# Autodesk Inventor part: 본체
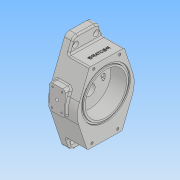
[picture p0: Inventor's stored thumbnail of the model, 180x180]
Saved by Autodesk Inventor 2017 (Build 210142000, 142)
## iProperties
Part Number: 본체
Material: 일반
Document SubType Name: Modeling
Designer: Administrator
Density: 1 g/cm^3
Appearance: 기본값
Author: Administrator
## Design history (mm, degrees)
sketch "스케치1"
  geometry: L1 (-51.832, 18.401)-(-24.317, 94); L2 (-24.317, 94)-(24.317, 94); L3 (24.317, 94)-(51.683, 18.811); L4 (-55, 0)-(55, 0); L5 (-33.78, 68)-(33.78, 68); L6 (-51.832, -18.401)-(-24.317, -94); L7 (-24.317, -94)-(24.317, -94); L8 (24.317, -94)-(51.683, -18.811); L9 (-33.78, -68)-(33.78, -68); A1 r 55 centre (0, 0) between (-51.683, 18.811) and (-55, 0); A2 r 55 centre (0, 0) between (-55, 0) and (-51.683, -18.811); A3 r 55 centre (0, 0) between (51.683, -18.811) and (51.683, 18.811); 3 further points
  constraints: 18 end point, 9 point on circle, 7 symmetric about line, 6 point on line, 5 tangent, 3 centre point, 3 horizontal, 1 coincident, 1 midpoint, 1 vertical alignment
  dimensions: "d2" = 40 deg angle of L3 L1; "d3" = 94 distance from line of point (0, 0) L2; "d4" = 110 distance of L4.start L4.end; "d5" = 68 distance between parallel lines of L4 L5
extrude "돌출1" new body sketch "스케치1" distance "d6" = 55; taper "d7" = 0 deg
extrude "돌출2" join sketch "스케치1" distance "d8" = 15; taper "d9" = 0 deg
sketch "스케치2"
  geometry: L1 (-94, 0)-(-94, 15) reference; L2 (-94, 15)-(-68, 15) reference; L3 (-68, 15)-(-68, 55) reference; L4 (-68, 55)-(68, 55) reference; L5 (68, 55)-(68, 15) reference; L6 (68, 15)-(94, 15) reference; L7 (94, 15)-(94, 0) reference; L8 (94, 0)-(-94, 0) reference; L9 (-94, 0)-(-94, 15) reference; L10 (-94, 15)-(-68, 15) reference; L11 (-68, 15)-(-68, 55) reference; L12 (-68, 55)-(68, 55) reference; L13 (68, 55)-(68, 15) reference; L14 (68, 15)-(94, 15) reference; L15 (94, 15)-(94, 0) reference; L16 (94, 0)-(-94, 0) reference; L17 (18.811, 55)-(-18.811, 55) reference; L18 (9, 0)-(9, 55); L19 (18.811, 55)-(68, 55) reference; L20 (49, 55)-(49, 25); L21 (49, 25)-(9, 25); L22 (49, 55)-(9, 55); 1 further point
  constraints: 8 end point, 4 point on line, 3 perpendicular, 1 collinear
  dimensions: "d10" = 9 distance from line of point (0, 0) L18; "d11" = 30 distance of L20.start L20.end; "d12" = 80 diameter of L20 L18
revolve "회전1" sketch "스케치2" stored, may be unused: angle "d13" = 90 deg
sketch "스케치8"
  geometry: L1 (-51.683, 18.811)-(-24.317, 94) reference; L2 (-24.317, 94)-(24.317, 94) reference; L3 (24.317, 94)-(51.683, 18.811) reference; L4 (51.683, -18.811)-(24.317, -94) reference; L5 (24.317, -94)-(-24.317, -94) reference; L6 (-24.317, -94)-(-51.683, -18.811) reference; C1 r 17.5 at (0, 0); A1 r 55 centre (0, 0) between (-51.683, 18.811) and (-51.683, -18.811) reference; A2 r 55 centre (0, 0) between (51.683, -18.811) and (51.683, 18.811) reference
  constraints: 1 centre point, 1 coincident
  dimensions: "d34" = 35 diameter of C1
extrude "돌출4" join sketch "스케치8" distance "d35" = 5; taper "d36" = 0 deg
sketch "스케치9"
  geometry: L1 (-94, 0)-(-94, 15) reference; L2 (-94, 15)-(-68, 15) reference; L3 (-68, 15)-(-68, 55) reference; L4 (-68, 55)-(-31, 55) reference; L5 (-31, 55)-(-31, 25) reference; L6 (-31, 25)-(49, 25) reference; L7 (49, 25)-(49, 55) reference; L8 (49, 55)-(68, 55) reference; L9 (68, 55)-(68, 15) reference; L10 (68, 15)-(94, 15) reference; L11 (94, 15)-(94, 0) reference; L12 (94, 0)-(17.5, 0) reference; L13 (17.5, 0)-(17.5, -5) reference; L14 (17.5, -5)-(-17.5, -5) reference; L15 (-17.5, -5)-(-17.5, 0) reference; L16 (-17.5, 0)-(-94, 0) reference; L17 (-17.5, -5)-(17.5, -5) reference; L18 (12.5, -5)-(12.5, 3.2); L19 (12.3, 3.4)-(8, 3.4); L20 (8, 3.4)-(8, 15); L21 (8, 15)-(10, 15); L22 (10, 15)-(10, 25); L23 (0, -5)-(0, 25); L24 (12.5, -5)-(0, -5); L25 (10, 25)-(0, 25); A1 r 0.2 centre (12.3, 3.2) between (12.5, 3.2) and (12.3, 3.4); 1 further point
  constraints: 16 end point, 4 perpendicular, 3 point on line, 2 collinear, 2 point on circle, 2 tangent, 2 vertical, 1 centre point, 1 midpoint
  dimensions: "d37" = 8.4 distance between parallel lines of L24 L19; "d38" = 10 distance between parallel lines of L25 L21; "d40" = 25 diameter of L18 L23; "d41" = 20 diameter of L22 L23; "d42" = 16 diameter of L20 L23; "d43" = 0.2 radius of A1 (derived)
revolve "회전3" sketch "스케치9" stored, may be unused: angle "d44" = 90 deg
node "작업 평면2"
sketch "스케치6"
  geometry: L1 (32, 35)-(-14, 35); L2 (-14, 35)-(-14, 5); L3 (-14, 5)-(32, 5); L4 (32, 5)-(32, 35); L5 (32, 35)-(-14, 5); L6 (-14, 35)-(32, 5); L7 (18.811, 0)-(-18.811, 0) reference; 2 further points
  constraints: 12 end point, 2 midpoint, 2 parallel, 1 horizontal, 1 perpendicular
  dimensions: "d26" = 30 distance of L3.end L1.start; "d27" = 46 distance of L2.end L3.end; "d29" = 20 distance from line of L7 point (9, 20); "d30" = 9 horizontal distance of point (0, 0) point (9, 20)
extrude "돌출3" join sketch "스케치6" stored distance "d31" = 4; taper "d32" = 0 deg
sketch "스케치10"
  geometry: L1 (33.78, -68)-(-33.78, -68) reference; L2 (-33.78, -68)-(-51.683, -18.811) reference; L3 (-51.683, 18.811)-(-33.78, 68) reference; L4 (-33.78, 68)-(33.78, 68) reference; L5 (33.78, 68)-(51.683, 18.811) reference; L6 (51.683, -18.811)-(33.78, -68) reference; L7 (33.78, -68)-(-33.78, -68) reference; L8 (-33.78, -68)-(-51.683, -18.811) reference; L9 (-51.683, 18.811)-(-33.78, 68) reference; L10 (-33.78, 68)-(33.78, 68) reference; L11 (33.78, 68)-(51.683, 18.811) reference; L12 (51.683, -18.811)-(33.78, -68) reference; C1 r 40 at (0, 9) reference; C2 r 40 at (0, 9) reference; C3 r 47.5 at (0, 9); C4 r 43.4 at (0, 9); A1 r 55 centre (0, 0) between (-51.683, 18.811) and (-51.683, -18.811) reference; A2 r 55 centre (0, 0) between (51.683, -18.811) and (51.683, 18.811) reference; A3 r 55 centre (0, 0) between (-51.683, 18.811) and (-51.683, -18.811) reference; A4 r 55 centre (0, 0) between (51.683, -18.811) and (51.683, 18.811) reference
  constraints: 2 centre point, 1 coincident
  dimensions: "d45" = 95 diameter of C3; "d46" = 4.1 radial gap between concentric circles of C3 C4
extrude "돌출5" cut sketch "스케치10" distance "d47" = 2.4; taper "d48" = 0 deg
sketch "스케치11"
  geometry: L1 (33.78, -77)-(-33.78, -77) reference; L2 (-33.78, -77)-(-51.683, -27.811) reference; L3 (-53.188, -23)-(-59, -23) reference; L4 (-59, -23)-(-59, 23) reference; L5 (-59, 23)-(-46.883, 23) reference; L6 (-46.883, 23)-(-33.78, 59) reference; L7 (-33.78, 59)-(33.78, 59) reference; L8 (33.78, 59)-(46.883, 23) reference; L9 (46.883, 23)-(59, 23) reference; L10 (59, 23)-(59, -23) reference; L11 (59, -23)-(53.188, -23) reference; L12 (51.683, -27.811)-(33.78, -77) reference; L13 (-26.702, -6)-(-25.515, -6); L14 (25.515, -6)-(26.702, -6); L15 (-26.702, 6)-(-22.517, 6); L16 (22.517, 6)-(26.702, 6); C1 r 40 at (0, 0) reference; C2 r 40 at (0, 0) reference; C3 r 10 at (0, -9) reference; C4 r 10 at (0, -9) reference; A1 r 55 centre (0, -9) between (-53.188, -23) and (-51.683, -27.811) reference; A2 r 55 centre (0, -9) between (51.683, -27.811) and (53.188, -23) reference; A3 r 24 centre (0, -9) between (-20.785, 3) and (-23.552, -4.385); A4 r 24 centre (0, -9) between (23.552, -4.385) and (20.785, 3); A5 r 29 centre (0, 0) between (-28.68, 4.296) and (-28.68, -4.296); A6 r 29 centre (0, 0) between (28.68, -4.296) and (28.68, 4.296); A7 r 2 centre (-22.517, 4) between (-20.785, 3) and (-22.517, 6); A8 r 2 centre (-26.702, 4) between (-26.702, 6) and (-28.68, 4.296); A9 r 2 centre (-26.702, -4) between (-28.68, -4.296) and (-26.702, -6); A10 r 2 centre (-25.515, -4) between (-25.515, -6) and (-23.552, -4.385); A11 r 2 centre (22.517, 4) between (22.517, 6) and (20.785, 3); A12 r 2 centre (26.702, 4) between (28.68, 4.296) and (26.702, 6); A13 r 2 centre (25.515, -4) between (23.552, -4.385) and (25.515, -6); A14 r 2 centre (26.702, -4) between (26.702, -6) and (28.68, -4.296); 8 further points
  constraints: 32 point on circle, 16 tangent, 12 centre point, 8 end point, 8 point on line, 7 equal radius, 4 horizontal, 2 coincident
  dimensions: "d53" = 6 distance from line of C1.centre L15; "d54" = 6 distance from line of C1.centre L16; "d55" = 6 distance from line of C1.centre L14; "d56" = 6 distance from line of L13 C1.centre; "d57" = 29 radius of A5; "d58" = 24 radius of A3; "d59" = 24 radius of A4; "d60" = 29 radius of A6; "d61" = 2 radius of A7
extrude "돌출6" cut sketch "스케치11" distance "d62" = 12; taper "d63" = 0 deg
sketch "스케치12"
  geometry: L1 (0, 0)-(-30, 0) reference; L2 (-30, 0)-(-30, 46) reference; L3 (-30, 46)-(0, 46) reference; L4 (0, 46)-(0, 0) reference; L5 (0, 46)-(0, 0) reference; L6 (0, 23)-(-30, 23); L7 (-30, 32.811)-(-30, 0) reference; L8 (0, 46)-(-30, 46) reference; L9 (-15, 46)-(-15, 0); C1 r 3 at (-15, 23); 1 further point
  constraints: 4 end point, 4 midpoint, 1 centre point, 1 perpendicular, 1 point on line
  dimensions: "d64" = 6 diameter of C1
extrude "돌출7" cut sketch "스케치12" stored distance "d65" = 12; taper "d66" = 0 deg; dims "d2" = 40 deg, "d3" = 94, "d4" = 110, "d5" = 68
sketch "스케치13"
  geometry: L1 (0, 0)-(-30, 0) reference; L2 (-30, 0)-(-30, 46) reference; L3 (-30, 46)-(0, 46) reference; L4 (0, 46)-(0, 0) reference; L5 (-24, 6)-(-6, 6); L6 (-6, 6)-(-6, 40); L7 (-6, 40)-(-24, 40); L8 (-24, 40)-(-24, 6); L9 (-24, 6)-(-6, 40); L10 (-6, 6)-(-24, 40); C1 r 3 at (-15, 23) reference; C2 r 3 at (-15, 23) reference; 5 further points
  constraints: 12 end point, 4 coincident, 2 midpoint, 2 parallel, 1 horizontal, 1 perpendicular
  dimensions: "d67" = 18 distance of L6.end L7.end; "d68" = 34 distance of L5.end L6.end
hole "구멍1" sketch "스케치13" at (-24, 40), (-6, 40), (-6, 6), (-24, 6) diameter "d69" = 3.242; stored, may be unused: countersink angle "d73" = 90 deg, drill point angle "d75" = 118 deg; dims "d70" = 8, "d71" = 4, "d72" = 2, "d74" = 10
sketch "스케치14"
  geometry: L1 (-22.517, 15)-(-26.702, 15) reference; L2 (-26.702, 3)-(-25.515, 3) reference; L3 (25.515, 3)-(26.702, 3) reference; L4 (26.702, 15)-(22.517, 15) reference; L5 (33.78, -68)-(-33.78, -68) reference; L6 (-24.317, -94)-(-33.78, -68) reference; L7 (24.317, -94)-(-24.317, -94) reference; L8 (33.78, -68)-(24.317, -94) reference; L9 (51.683, -18.811)-(33.78, -68) reference; L10 (59, -14)-(53.188, -14) reference; L11 (59, 32)-(59, -14) reference; L12 (46.883, 32)-(59, 32) reference; L13 (33.78, 68)-(46.883, 32) reference; L14 (-33.78, 68)-(33.78, 68) reference; L15 (-46.883, 32)-(-33.78, 68) reference; L16 (-59, 32)-(-46.883, 32) reference; L17 (-59, -14)-(-59, 32) reference; L18 (-53.188, -14)-(-59, -14) reference; L19 (-33.78, -68)-(-51.683, -18.811) reference; L20 (24.317, 94)-(33.78, 68) reference; L21 (-24.317, 94)-(24.317, 94) reference; L22 (-33.78, 68)-(-24.317, 94) reference; L23 (-20, -79)-(20, -79); L24 (20, -79)-(20, 79); L25 (20, 79)-(-20, 79); L26 (-20, 79)-(-20, -79); L27 (-20, -79)-(20, 79); L28 (20, -79)-(-20, 79); C1 r 8 at (0, 0) reference; C2 r 10 at (0, 0) reference; C3 r 12.5 at (0, 0) reference; A1 r 2 centre (-26.702, 13) between (-26.702, 15) and (-28.68, 13.296) reference; A2 r 29 centre (0, 9) between (-28.68, 13.296) and (-28.68, 4.704) reference; A3 r 2 centre (-26.702, 5) between (-28.68, 4.704) and (-26.702, 3) reference; A4 r 2 centre (-25.515, 5) between (-25.515, 3) and (-23.552, 4.615) reference; A5 r 24 centre (0, 0) between (-20.785, 12) and (-23.552, 4.615) reference; A6 r 2 centre (-22.517, 13) between (-20.785, 12) and (-22.517, 15) reference; A7 r 24 centre (0, 0) between (23.552, 4.615) and (20.785, 12) reference; A8 r 2 centre (25.515, 5) between (23.552, 4.615) and (25.515, 3) reference; A9 r 2 centre (26.702, 5) between (26.702, 3) and (28.68, 4.704) reference; A10 r 29 centre (0, 9) between (28.68, 4.704) and (28.68, 13.296) reference; A11 r 2 centre (26.702, 13) between (28.68, 13.296) and (26.702, 15) reference; A12 r 2 centre (22.517, 13) between (22.517, 15) and (20.785, 12) reference; A13 r 55 centre (0, 0) between (51.683, -18.811) and (53.188, -14) reference; A14 r 55 centre (0, 0) between (-53.188, -14) and (-51.683, -18.811) reference; 5 further points
  constraints: 12 end point, 4 coincident, 2 midpoint, 2 parallel, 1 horizontal, 1 perpendicular
  dimensions: "d76" = 40 distance of L24.end L25.end; "d77" = 158 distance of L23.end L24.end
hole "구멍2" sketch "스케치14" at (-20, 79), (20, 79), (-20, -79), (20, -79) diameter "d78" = 6.6; stored, may be unused: countersink angle "d82" = 90 deg, drill point angle "d84" = 118 deg; dims "d79" = 8, "d80" = 11, "d81" = 6.6, "d83" = 10
sketch "스케치15"
  geometry: L1 (33.78, -68)-(-33.78, -68) reference; L2 (-33.78, -68)-(-51.683, -18.811) reference; L3 (-51.683, 18.811)-(-33.78, 68) reference; L4 (-33.78, 68)-(33.78, 68) reference; L5 (33.78, 68)-(51.683, 18.811) reference; L6 (51.683, -18.811)-(33.78, -68) reference; L7 (-25, -61)-(25, -61); L8 (25, -61)-(25, 61); L9 (25, 61)-(-25, 61); L10 (-25, 61)-(-25, -61); L11 (-25, -61)-(25, 61); L12 (25, -61)-(-25, 61); C1 r 43.4 at (0, 9) reference; C2 r 47.5 at (0, 9) reference; C3 r 40 at (0, 9) reference; A1 r 55 centre (0, 0) between (-51.683, 18.811) and (-51.683, -18.811) reference; A2 r 55 centre (0, 0) between (51.683, -18.811) and (51.683, 18.811) reference; 4 further points
  constraints: 12 end point, 4 coincident, 2 midpoint, 2 parallel, 1 horizontal, 1 perpendicular
  dimensions: "d85" = 50 distance of L8.end L9.end; "d86" = 122 distance of L7.end L8.end
hole "구멍3" sketch "스케치15" at (-25, 61), (25, 61), (-25, -61), (25, -61) diameter "d87" = 4.917; stored, may be unused: countersink angle "d91" = 90 deg, drill point angle "d93" = 118 deg; dims "d88" = 12, "d89" = 11, "d90" = 6.6, "d92" = 14
sketch "스케치16"
  geometry: L1 (-22.517, 6)-(-26.702, 6) reference; L2 (-26.702, -6)-(-25.515, -6) reference; L3 (25.515, -6)-(26.702, -6) reference; L4 (26.702, 6)-(22.517, 6) reference; L5 (33.78, -77)-(-33.78, -77) reference; L6 (-33.78, -77)-(-51.683, -27.811) reference; L7 (-53.188, -23)-(-59, -23) reference; L8 (-59, -23)-(-59, 23) reference; L9 (-59, 23)-(-46.883, 23) reference; L10 (-46.883, 23)-(-33.78, 59) reference; L11 (-33.78, 59)-(33.78, 59) reference; L12 (33.78, 59)-(46.883, 23) reference; L13 (46.883, 23)-(59, 23) reference; L14 (59, 23)-(59, -23) reference; L15 (59, -23)-(53.188, -23) reference; L16 (51.683, -27.811)-(33.78, -77) reference; C1 r 40 at (0, 0) reference; C2 r 10 at (0, -9) reference; A1 r 24 centre (0, -9) between (-20.785, 3) and (-23.552, -4.385) reference; A2 r 24 centre (0, -9) between (23.552, -4.385) and (20.785, 3) reference; A3 r 2 centre (-26.702, 4) between (-26.702, 6) and (-28.68, 4.296) reference; A4 r 29 centre (0, 0) between (-28.68, 4.296) and (-28.68, -4.296) reference; A5 r 2 centre (-26.702, -4) between (-28.68, -4.296) and (-26.702, -6) reference; A6 r 2 centre (-25.515, -4) between (-25.515, -6) and (-23.552, -4.385) reference; A7 r 24 centre (0, -9) between (-20.785, 3) and (-23.552, -4.385) reference; A8 r 2 centre (-22.517, 4) between (-20.785, 3) and (-22.517, 6) reference; A9 r 24 centre (0, -9) between (23.552, -4.385) and (20.785, 3) reference; A10 r 2 centre (25.515, -4) between (23.552, -4.385) and (25.515, -6) reference; A11 r 2 centre (26.702, -4) between (26.702, -6) and (28.68, -4.296) reference; A12 r 29 centre (0, 0) between (28.68, -4.296) and (28.68, 4.296) reference; A13 r 2 centre (26.702, 4) between (28.68, 4.296) and (26.702, 6) reference; A14 r 2 centre (22.517, 4) between (22.517, 6) and (20.785, 3) reference; A15 r 55 centre (0, -9) between (-53.188, -23) and (-51.683, -27.811) reference; A16 r 55 centre (0, -9) between (51.683, -27.811) and (53.188, -23) reference; 2 further points
  dimensions: "d94" = 26 vertical distance of A2.centre point (-15, 17); "d95" = 26 vertical distance of A1.centre point (15, 17); "d96" = 15 horizontal distance of A1.centre point (15, 17); "d97" = 15 horizontal distance of point (-15, 17) A1.centre
hole "구멍4" sketch "스케치16" at (-15, 17), (15, 17) diameter "d98" = 3.242; stored, may be unused: countersink angle "d102" = 90 deg, drill point angle "d104" = 118 deg; dims "d99" = 8, "d100" = 11, "d101" = 6.6, "d103" = 10
fillet "모깎기1" dims "d105" = 10
fillet "모깎기2" dims "d106" = 5
fillet "모깎기3" dims "d107" = 0.5
fillet "모깎기4" dims "d108" = 3
fillet "모깎기5" dims "d109" = 3
fillet "모깎기7" dims "d111" = 3
chamfer "모따기3" distance "d118" = 0.4; stored, may be unused: second distance "d119" = 2, angle "d120" = 30 deg
chamfer "모따기4" distance "d121" = 1; stored, may be unused: second distance "d122" = 2, angle "d123" = 30 deg
sketch "스케치17"
  geometry: L1 (63.358, 0)-(0, 0) reference; L2 (63.358, 0)-(0, 0) reference; L3 (0, 37)-(0, 0) reference; L4 (0, 37)-(63.358, 37) reference; L5 (63.358, 37)-(63.358, 0) reference; L6 (-2.101, 41.449)-(-2.101, 55) reference; L7 (-2.101, 55)-(65.459, 55) reference; L8 (65.459, 55)-(65.459, 41.449) reference; L9 (-17.947, 28.35)-(81.305, 28.35); L10 (81.305, 28.35)-(81.305, 1.65); L11 (81.305, 1.65)-(-17.947, 1.65); L12 (-17.947, 1.65)-(-17.947, 28.35); L13 (-17.947, 15)-(81.305, 15); L14 (31.679, 28.35)-(31.679, 1.65); 2 further points
  constraints: 5 midpoint, 4 end point, 1 vertical alignment, 4 other
  dimensions: "d124" = 15 distance between parallel lines of L1 L13
feature "엠보싱1" sketch "스케치17" dims "d2" = 40 deg, "d3" = 94, "d4" = 110, "d5" = 68, "d125" = 0.5, "d126" = 0
node "솔리드1"
mirror "미러1"
mirror "미러2"
mirror "미러3"
node "절단 모서리 투영1"
node "절단 모서리 투영2"
node "절단 모서리 투영5"
node "절단 모서리 투영6"
node "절단 모서리 투영7"
node "절단 모서리 투영8"
node "절단 모서리 투영9"
node "절단 모서리 투영10"
node "절단 모서리 투영11"
node "절단 모서리 투영12"
node "절단 모서리 투영13"
node "절단 모서리 투영14"
node "절단 모서리 투영15"
other parameters: "d25" = 59, "d49" = 58, "d50" = 48, "d51" = 6, "d52" = 6
